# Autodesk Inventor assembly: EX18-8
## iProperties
Author: Elise Moss
Revision Number: A
Created: 2001-09
Part Number: EX18-8
Description: ASSY, DRILL PRESS
Document SubType Name: Assembly
Designer: Elise Moss
Control State: 0
Master: False
Checked Out: False
PropertySet Name: Design Tracking Control
Length Units: 11272
Angle Units: 11279
Time Units: 11290
Mass Units: 11286
Shininess: 3
Angle Display Precision: 2
Document Length Units: 11272
Document Angle Units: 11286
Document Time Units: 11279
Document Mass Units: 11290
Document Length Units Precision: 3
Document Angle Units Precision: 2
Compacted: False
PropertySet Name: _Private Model Information
Density: 0.0
Volumn: 0.0
Area: 0.0
PropertySet Name: Model Information
